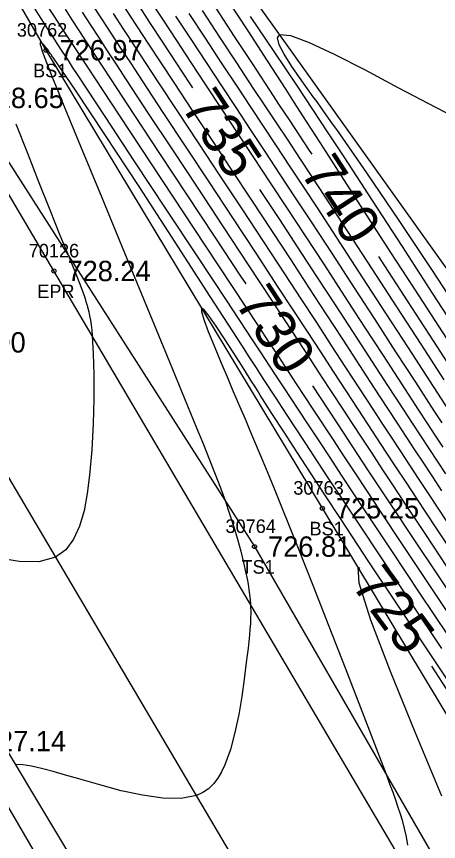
# Model space of a CAD drawing. Extents: x 1376587 to 1378239, y 1000335 to 1003031.
# Drawn here: x 1377030.7 to 1377061.8, y 1002189 to 1002249.8 of the extents above; entities that cross this region are included whole.
import ezdxf

# ---------------------------------------------------------------- set-up
doc = ezdxf.new("R2010")
doc.units = 0
for name, color, linetype in [('RD_DTM_BkLn1', 7, 'Continuous'), ('RD_DTM_BkLn2', 7, 'Continuous'), ('RD_DTM_BkLn_txCode', 7, 'Continuous'), ('RD_DTM_Major1', 7, 'Continuous'), ('RD_DTM_Major1_Lbl', 7, 'Continuous'), ('RD_DTM_Minor1', 7, 'Continuous'), ('RD_EX_Road', 7, 'Continuous'), ('RD_EX_Road_txCode', 7, 'Continuous'), ('RD_EX_TX_Misc_ELEV', 7, 'Continuous'), ('RD_EX_TX_Road_ELEV', 7, 'Continuous'), ('RD_HC_Survey_ELEV', 7, 'Continuous'), ('RD_SMD_Locator', 7, 'Continuous')]:
    doc.layers.add(name, color=color, linetype=linetype)

msp = doc.modelspace()

# ---------------------------------------------------------------- linework, layer by layer
at = {"layer": 'RD_DTM_BkLn1'}
msp.add_lwpolyline([(1377340.411, 1001702.156), (1377308.865, 1001753.727), (1377278.246, 1001805.238), (1377245.962, 1001858.008), (1377214.824, 1001910.42), (1377182.966, 1001962.109), (1377151.242, 1002015.115), (1377120.387, 1002065.538), (1377089.615, 1002116.564), (1377055.769, 1002172.475), (1377024.269, 1002225.826), (1377004.131, 1002257.876), (1377003.447, 1002259.314)], dxfattribs=at)
at = {"layer": 'RD_DTM_BkLn2'}
for points in [[(1377334.808, 1002026.055), (1377284.229, 1002013.339), (1377249.257, 1001988.727), (1377213.659, 1001973.589), (1377188.957, 1002014.33), (1377158.44, 1002070.963), (1377139.047, 1002104.941), (1377113.892, 1002149.475), (1377071.66, 1002218.399), (1377041.895, 1002260.076), (1377023.693, 1002288.088), (1377010.927, 1002302.495), (1376992.725, 1002332.02), (1376976.352, 1002351.559)], [(1376977.592, 1002343.743), (1376991.525, 1002318.779), (1377012.226, 1002283.102), (1377032.893, 1002247.364), (1377053.281, 1002213.6), (1377075.695, 1002176.413), (1377096.747, 1002142.056), (1377117.513, 1002106.979), (1377138.493, 1002071.226), (1377160.243, 1002035.712), (1377181.074, 1001999.107), (1377204.311, 1001959.476)], [(1376971.766, 1002339.684), (1376984.16, 1002314.581), (1377005.368, 1002280.112), (1377027.082, 1002243.848), (1377048.279, 1002210.776), (1377069.87, 1002173.423), (1377092.065, 1002138.92), (1377112.017, 1002104.252), (1377133.641, 1002068.495), (1377155.53, 1002032.726), (1377177.087, 1001996.618), (1377201.678, 1001958.67), (1377205.328, 1001957.618)], [(1376933.477, 1002336.978), (1376936.207, 1002337.361), (1376942.118, 1002334.622), (1376963.252, 1002302.727), (1376984.874, 1002266.163), (1377004.611, 1002231.868), (1377027.248, 1002196.435), (1377047.864, 1002161.082), (1377069.437, 1002124.09), (1377090.339, 1002090.957), (1377112.039, 1002054.903), (1377133.555, 1002020.982), (1377142.847, 1002000.419), (1377146.96, 1001979.874), (1377168.451, 1001949.096), (1377180.608, 1001931.393), (1377190.285, 1001911.959), (1377184.466, 1001904.154), (1377176.345, 1001916.445), (1377168.914, 1001925.218), (1377157.418, 1001940.596), (1377135.248, 1001988.16)]]:
    msp.add_lwpolyline(points, dxfattribs=at)
at = {"layer": 'RD_DTM_Major1'}
for points in [[(1377047.654, 1002230.136), (1377047.278, 1002230.706), (1377045.332, 1002233.655), (1377043.313, 1002236.712), (1377041.307, 1002239.747), (1377039.402, 1002242.635), (1377037.683, 1002245.247), (1377036.45, 1002247.128), (1377035.887, 1002247.991), (1377035.351, 1002248.815), (1377034.836, 1002249.609), (1377034.335, 1002250.385)], [(1377039.619, 1002250.823), (1377040.539, 1002249.408), (1377041.491, 1002247.952), (1377042.479, 1002246.45), (1377043.503, 1002244.897), (1377043.699, 1002244.599)], [(1377052.52, 1002239.698), (1377052.342, 1002239.969), (1377051.592, 1002241.11), (1377050.859, 1002242.222), (1377050.133, 1002243.323), (1377049.403, 1002244.431), (1377048.122, 1002246.374), (1377046.801, 1002248.384), (1377045.448, 1002250.456)], [(1377048.659, 1002237.089), (1377048.743, 1002236.961), (1377050.111, 1002234.884), (1377051.48, 1002232.797), (1377052.863, 1002230.683), (1377054.226, 1002228.592), (1377055.558, 1002226.545), (1377058.086, 1002222.657), (1377059.26, 1002220.855), (1377059.897, 1002219.88), (1377060.517, 1002218.933), (1377061.129, 1002218.001), (1377061.74, 1002217.072), (1377062.358, 1002216.135)], [(1377063.278, 1002223.158), (1377061.471, 1002225.943), (1377059.555, 1002228.897), (1377057.609, 1002231.895), (1377057.437, 1002232.16)], [(1377063.681, 1002205.847), (1377061.837, 1002208.615), (1377060.059, 1002211.29), (1377058.41, 1002213.774), (1377056.693, 1002216.37), (1377055.907, 1002217.56), (1377055.156, 1002218.702), (1377054.426, 1002219.812), (1377053.708, 1002220.907), (1377052.592, 1002222.612)], [(1377056.038, 1002209.158), (1377055.896, 1002209.261), (1377055.967, 1002208.09), (1377056.836, 1002205.385), (1377058.287, 1002201.579), (1377060.105, 1002197.107), (1377062.074, 1002192.404)], [(1377062.661, 1002199.943), (1377061.366, 1002201.963)]]:
    msp.add_lwpolyline(points, dxfattribs=at)
at = {"layer": 'RD_DTM_Minor1'}
for points in [[(1377040.497, 1002251.188), (1377041.5, 1002249.644), (1377042.531, 1002248.068), (1377043.589, 1002246.459), (1377044.673, 1002244.817), (1377045.828, 1002243.067), (1377047.01, 1002241.28), (1377048.215, 1002239.455), (1377049.444, 1002237.593), (1377050.693, 1002235.694), (1377051.963, 1002233.758), (1377053.43, 1002231.513), (1377054.9, 1002229.257), (1377056.351, 1002227.025), (1377057.763, 1002224.852), (1377059.114, 1002222.773), (1377060.383, 1002220.825), (1377060.995, 1002219.888), (1377061.588, 1002218.982), (1377062.167, 1002218.099)], [(1377062.452, 1002226.103), (1377060.413, 1002229.248), (1377058.34, 1002232.452), (1377056.326, 1002235.57), (1377054.467, 1002238.454), (1377053.774, 1002239.53), (1377053.113, 1002240.558), (1377052.475, 1002241.551), (1377051.85, 1002242.523), (1377051.231, 1002243.488), (1377050.607, 1002244.461), (1377049.243, 1002246.582), (1377047.817, 1002248.781), (1377046.329, 1002251.04)], [(1377062.58, 1002204.189), (1377060.477, 1002207.347), (1377058.453, 1002210.39), (1377056.596, 1002213.187), (1377055.612, 1002214.673), (1377054.701, 1002216.049), (1377053.85, 1002217.339), (1377053.042, 1002218.563), (1377052.264, 1002219.744), (1377051.5, 1002220.904), (1377050.987, 1002221.685), (1377050.465, 1002222.478), (1377049.926, 1002223.297), (1377049.363, 1002224.152), (1377048.767, 1002225.057), (1377048.129, 1002226.024), (1377046.208, 1002228.93), (1377044.048, 1002232.195), (1377041.761, 1002235.651), (1377039.461, 1002239.132), (1377037.261, 1002242.469), (1377035.273, 1002245.497), (1377034.867, 1002246.118), (1377034.476, 1002246.717), (1377034.097, 1002247.298), (1377033.73, 1002247.863), (1377033.372, 1002248.416), (1377033.021, 1002248.957), (1377032.068, 1002250.44)], [(1377063.13, 1002205.019), (1377061.156, 1002207.983), (1377059.253, 1002210.843), (1377057.5, 1002213.485), (1377056.563, 1002214.899), (1377055.692, 1002216.216), (1377054.874, 1002217.456), (1377054.095, 1002218.638), (1377052.606, 1002220.905), (1377051.996, 1002221.835), (1377051.376, 1002222.781), (1377050.735, 1002223.759), (1377050.062, 1002224.785), (1377049.346, 1002225.876), (1377048.575, 1002227.047), (1377046.713, 1002229.874), (1377044.652, 1002232.994), (1377038.34, 1002242.538), (1377036.544, 1002245.255), (1377036.024, 1002246.042), (1377035.534, 1002246.785), (1377035.07, 1002247.488), (1377034.628, 1002248.161), (1377034.202, 1002248.809), (1377033.789, 1002249.44), (1377033.013, 1002250.632)], [(1377063.211, 1002209.865), (1377061.68, 1002212.167), (1377060.245, 1002214.33), (1377059.46, 1002215.517), (1377058.713, 1002216.649), (1377057.995, 1002217.738), (1377057.296, 1002218.801), (1377056.606, 1002219.853), (1377055.916, 1002220.907), (1377055.027, 1002222.267), (1377054.114, 1002223.668), (1377053.166, 1002225.12), (1377052.177, 1002226.637), (1377051.136, 1002228.228), (1377050.036, 1002229.907), (1377048.399, 1002232.396), (1377046.681, 1002235.003), (1377044.931, 1002237.653), (1377041.544, 1002242.782), (1377040.008, 1002245.112), (1377039.195, 1002246.348), (1377038.432, 1002247.511), (1377037.711, 1002248.613), (1377037.025, 1002249.669), (1377036.365, 1002250.689)], [(1377038.748, 1002250.449), (1377039.587, 1002249.158), (1377040.462, 1002247.821), (1377041.376, 1002246.429), (1377042.336, 1002244.972), (1377043.686, 1002242.926), (1377045.103, 1002240.781), (1377046.565, 1002238.568), (1377048.05, 1002236.318), (1377049.535, 1002234.063), (1377050.999, 1002231.834), (1377052.292, 1002229.857), (1377053.548, 1002227.932), (1377054.763, 1002226.066), (1377057.062, 1002222.534), (1377058.141, 1002220.879), (1377058.799, 1002219.873), (1377059.444, 1002218.888), (1377060.087, 1002217.909), (1377060.734, 1002216.926), (1377061.396, 1002215.923), (1377062.079, 1002214.89)], [(1377044.413, 1002250.28), (1377045.686, 1002248.335), (1377046.949, 1002246.423), (1377048.19, 1002244.55), (1377049.036, 1002243.275), (1377049.877, 1002242.005), (1377050.727, 1002240.721), (1377051.596, 1002239.404), (1377052.496, 1002238.036), (1377053.439, 1002236.598), (1377055.136, 1002233.998), (1377056.927, 1002231.247), (1377058.747, 1002228.442), (1377060.536, 1002225.685), (1377062.231, 1002223.074)], [(1377062.523, 1002209.242), (1377060.869, 1002211.73), (1377059.327, 1002214.054), (1377058.49, 1002215.317), (1377057.701, 1002216.511), (1377056.949, 1002217.652), (1377056.223, 1002218.755), (1377055.514, 1002219.836), (1377054.81, 1002220.91), (1377054.015, 1002222.125), (1377053.203, 1002223.368), (1377052.362, 1002224.656), (1377051.481, 1002226.004), (1377050.548, 1002227.429), (1377049.552, 1002228.947), (1377047.838, 1002231.553), (1377046.004, 1002234.333), (1377044.12, 1002237.185), (1377042.254, 1002240.011), (1377040.473, 1002242.708), (1377038.847, 1002245.178), (1377038.117, 1002246.287), (1377037.435, 1002247.329), (1377036.791, 1002248.314), (1377036.179, 1002249.254), (1377035.591, 1002250.162)], [(1377062.492, 1002212.604), (1377061.163, 1002214.608), (1377060.429, 1002215.718), (1377059.725, 1002216.785), (1377059.041, 1002217.823), (1377058.37, 1002218.845), (1377057.701, 1002219.865), (1377057.026, 1002220.896), (1377056.043, 1002222.404), (1377055.024, 1002223.967), (1377053.966, 1002225.591), (1377052.865, 1002227.28), (1377051.717, 1002229.038), (1377050.518, 1002230.87), (1377048.965, 1002233.234), (1377047.362, 1002235.665), (1377045.746, 1002238.114), (1377044.152, 1002240.527), (1377042.615, 1002242.854), (1377041.171, 1002245.044), (1377040.282, 1002246.395), (1377039.442, 1002247.674), (1377038.644, 1002248.894), (1377037.882, 1002250.065)], [(1377042.464, 1002249.868), (1377043.576, 1002248.171), (1377044.703, 1002246.458), (1377045.843, 1002244.733), (1377046.898, 1002243.138), (1377047.964, 1002241.526), (1377049.047, 1002239.887), (1377050.152, 1002238.212), (1377051.285, 1002236.49), (1377052.45, 1002234.712), (1377053.997, 1002232.345), (1377055.573, 1002229.924), (1377057.146, 1002227.503), (1377058.682, 1002225.138), (1377060.147, 1002222.882), (1377061.509, 1002220.791), (1377062.093, 1002219.896)], [(1377043.437, 1002250.08), (1377044.629, 1002248.26), (1377045.824, 1002246.446), (1377047.015, 1002244.646), (1377047.967, 1002243.209), (1377048.92, 1002241.769), (1377049.884, 1002240.31), (1377050.869, 1002238.816), (1377051.885, 1002237.272), (1377052.942, 1002235.66), (1377054.565, 1002233.175), (1377056.248, 1002230.589), (1377057.944, 1002227.977), (1377059.606, 1002225.417), (1377061.186, 1002222.983), (1377062.637, 1002220.752)], [(1377063.563, 1002226.144), (1377061.417, 1002229.461), (1377059.195, 1002232.892), (1377056.989, 1002236.287), (1377054.893, 1002239.494), (1377054.301, 1002240.394), (1377053.723, 1002241.272), (1377053.154, 1002242.134), (1377052.587, 1002242.988), (1377052.02, 1002243.842), (1377051.446, 1002244.703), (1377049.734, 1002247.258), (1377047.982, 1002249.86)], [(1377063.826, 1002227.428), (1377061.402, 1002231.114), (1377058.945, 1002234.805), (1377056.558, 1002238.331), (1377054.343, 1002241.52), (1377054.04, 1002241.948), (1377053.743, 1002242.366), (1377053.452, 1002242.773), (1377053.167, 1002243.169), (1377052.889, 1002243.556), (1377052.617, 1002243.933), (1377051.765, 1002245.118), (1377051.032, 1002246.17), (1377050.46, 1002247.063), (1377050.093, 1002247.77), (1377049.974, 1002248.266), (1377050.146, 1002248.523), (1377050.937, 1002248.456), (1377052.304, 1002247.944), (1377054.151, 1002247.074), (1377056.384, 1002245.931), (1377058.906, 1002244.603), (1377061.622, 1002243.174), (1377065.499, 1002241.168)], [(1377062.083, 1002203.27), (1377059.869, 1002206.591), (1377057.74, 1002209.787), (1377055.797, 1002212.711), (1377054.771, 1002214.257), (1377053.821, 1002215.692), (1377052.923, 1002217.052), (1377052.054, 1002218.371), (1377051.193, 1002219.686), (1377050.315, 1002221.03), (1377049.869, 1002221.716), (1377048.929, 1002223.164), (1377048.426, 1002223.939), (1377047.896, 1002224.758), (1377047.334, 1002225.627), (1377045.017, 1002229.21), (1377042.424, 1002233.215), (1377039.764, 1002237.306), (1377037.247, 1002241.15), (1377035.083, 1002244.411), (1377033.482, 1002246.754), (1377033.434, 1002246.822), (1377033.388, 1002246.888), (1377033.342, 1002246.952), (1377033.297, 1002247.014), (1377033.212, 1002247.133), (1377033.062, 1002247.338), (1377032.929, 1002247.514), (1377032.814, 1002247.662), (1377032.715, 1002247.779), (1377032.633, 1002247.868), (1377032.568, 1002247.926), (1377032.519, 1002247.955), (1377032.486, 1002247.953), (1377032.47, 1002247.921), (1377032.469, 1002247.859), (1377032.482, 1002247.77), (1377032.51, 1002247.653), (1377032.627, 1002247.282), (1377032.811, 1002246.775), (1377033.057, 1002246.137), (1377033.363, 1002245.376), (1377033.721, 1002244.496), (1377034.128, 1002243.504), (1377035.455, 1002240.281), (1377037.008, 1002236.51), (1377038.687, 1002232.437), (1377040.388, 1002228.312), (1377042.008, 1002224.382), (1377044.004, 1002219.539), (1377044.511, 1002218.301), (1377044.97, 1002217.163), (1377045.386, 1002216.106), (1377045.765, 1002215.111), (1377046.111, 1002214.159), (1377046.446, 1002213.178), (1377046.75, 1002212.228), (1377047.021, 1002211.313), (1377047.261, 1002210.436), (1377047.469, 1002209.603), (1377047.645, 1002208.817), (1377047.729, 1002208.404), (1377047.802, 1002208.004), (1377047.865, 1002207.617), (1377047.916, 1002207.24), (1377047.955, 1002206.872), (1377047.982, 1002206.511), (1377047.992, 1002206.277), (1377047.997, 1002206.045), (1377047.998, 1002205.812), (1377047.993, 1002205.577), (1377047.985, 1002205.339), (1377047.972, 1002205.096), (1377047.942, 1002204.674), (1377047.903, 1002204.232), (1377047.855, 1002203.769), (1377047.8, 1002203.28), (1377047.738, 1002202.765), (1377047.671, 1002202.219), (1377047.519, 1002201.011), (1377047.337, 1002199.717), (1377047.114, 1002198.388), (1377046.839, 1002197.073), (1377046.5, 1002195.822), (1377046.087, 1002194.686), (1377045.843, 1002194.167), (1377045.568, 1002193.697), (1377045.254, 1002193.281), (1377044.892, 1002192.925), (1377044.476, 1002192.635), (1377043.995, 1002192.416), (1377042.86, 1002192.201), (1377041.514, 1002192.226), (1377040.022, 1002192.438), (1377038.45, 1002192.781), (1377036.862, 1002193.202), (1377035.324, 1002193.645), (1377034.339, 1002193.932), (1377033.419, 1002194.192), (1377032.579, 1002194.411), (1377031.831, 1002194.577), (1377031.188, 1002194.678), (1377030.663, 1002194.7)], [(1377030.679, 1002241.929), (1377031.526, 1002239.764), (1377032.374, 1002237.623), (1377033.188, 1002235.588), (1377033.934, 1002233.738), (1377034.578, 1002232.153), (1377034.878, 1002231.415), (1377035.14, 1002230.767), (1377035.367, 1002230.194), (1377035.563, 1002229.68), (1377035.731, 1002229.208), (1377035.874, 1002228.765), (1377035.895, 1002228.695), (1377035.915, 1002228.626), (1377035.935, 1002228.557), (1377035.954, 1002228.488), (1377035.973, 1002228.419), (1377035.992, 1002228.349), (1377036.06, 1002228.071), (1377036.121, 1002227.779), (1377036.177, 1002227.464), (1377036.226, 1002227.118), (1377036.27, 1002226.733), (1377036.31, 1002226.301), (1377036.386, 1002225.004), (1377036.428, 1002223.44), (1377036.428, 1002221.684), (1377036.381, 1002219.815), (1377036.28, 1002217.908), (1377036.118, 1002216.04), (1377035.944, 1002214.678), (1377035.706, 1002213.416), (1377035.378, 1002212.286), (1377034.936, 1002211.319), (1377034.356, 1002210.546), (1377033.613, 1002210), (1377032.384, 1002209.655), (1377030.915, 1002209.664), (1377029.284, 1002209.943)], [(1377063.846, 1002198.954), (1377061.486, 1002202.491), (1377059.092, 1002206.086), (1377056.768, 1002209.586), (1377054.615, 1002212.841), (1377053.464, 1002214.589), (1377052.397, 1002216.219), (1377051.399, 1002217.75), (1377050.459, 1002219.202), (1377049.564, 1002220.594), (1377048.701, 1002221.946), (1377048.496, 1002222.269), (1377048.292, 1002222.59), (1377048.089, 1002222.911), (1377047.685, 1002223.549), (1377047.484, 1002223.867), (1377046.754, 1002225.02), (1377046.063, 1002226.097), (1377045.446, 1002227.034), (1377044.936, 1002227.766), (1377044.566, 1002228.229), (1377044.369, 1002228.36), (1377044.369, 1002228.105), (1377044.548, 1002227.506), (1377044.871, 1002226.635), (1377045.3, 1002225.565), (1377045.797, 1002224.37), (1377046.327, 1002223.121), (1377046.642, 1002222.382), (1377046.956, 1002221.648), (1377047.27, 1002220.915), (1377047.583, 1002220.182), (1377047.896, 1002219.446), (1377048.211, 1002218.703), (1377048.705, 1002217.528), (1377049.209, 1002216.315), (1377049.729, 1002215.05), (1377050.273, 1002213.716), (1377050.846, 1002212.296), (1377051.455, 1002210.775), (1377052.581, 1002207.938), (1377053.772, 1002204.911), (1377054.968, 1002201.848), (1377056.107, 1002198.905), (1377057.132, 1002196.234), (1377057.981, 1002193.991), (1377058.241, 1002193.294), (1377058.471, 1002192.666), (1377058.675, 1002192.094), (1377058.855, 1002191.568), (1377059.015, 1002191.074), (1377059.158, 1002190.601), (1377059.324, 1002189.989), (1377059.461, 1002189.381), (1377059.566, 1002188.763)]]:
    msp.add_lwpolyline(points, dxfattribs=at)
at = {"layer": 'RD_EX_Road'}
for points in [[(1377350.339, 1001708.261), (1377317.923, 1001758.892), (1377286.961, 1001809.893), (1377254.767, 1001863.401), (1377224.604, 1001914.857), (1377192.26, 1001967.361), (1377160.973, 1002019.841), (1377129.715, 1002070.663), (1377099.389, 1002121.709), (1377064.159, 1002179.082), (1377033.485, 1002231.09), (1377014.7, 1002262.97), (1377013.314, 1002264.907)], [(1377330.916, 1001696.377), (1377301.062, 1001747.923), (1377269.086, 1001800.224), (1377238.031, 1001851.797), (1377206.51, 1001905.086), (1377174.784, 1001956.207), (1377142.237, 1002010.206), (1377112.371, 1002059.861), (1377081.07, 1002112.138), (1377047.747, 1002166.267), (1377015.04, 1002220.702), (1376995.387, 1002252.515), (1376994.747, 1002253.913)]]:
    msp.add_lwpolyline(points, dxfattribs=at)
at = {"layer": 'RD_SMD_Locator'}
for centre in [(1377032.893, 1002247.364), (1377033.485, 1002231.09), (1377053.281, 1002213.6), (1377048.279, 1002210.776)]:
    msp.add_circle(centre, 0.15, dxfattribs=at)

# ---------------------------------------------------------------- texts
at = {"layer": 'RD_DTM_BkLn_txCode'}
for s, p in [('30762', (1377030.751, 1002248.364)), ('BS1', (1377031.948, 1002245.364)), ('30763', (1377051.139, 1002214.6)), ('30764', (1377046.137, 1002211.776)), ('BS1', (1377052.336, 1002211.6)), ('TS1', (1377047.318, 1002208.776))]:
    msp.add_text(s, height=1, dxfattribs=at).set_placement(p)
at = {"layer": 'RD_DTM_Major1_Lbl'}
for s, rotation, p in [('735', 303.43973, (1377042.806, 1002243.231)), ('740', 303.114, (1377051.597, 1002238.377)), ('730', 303.27796, (1377046.76, 1002228.772)), ('725', 306.52157, (1377055.361, 1002207.957))]:
    msp.add_text(s, height=3, rotation=rotation, dxfattribs=at).set_placement(p)
at = {"layer": 'RD_EX_Road_txCode'}
for s, p in [('70126', (1377031.627, 1002232.09)), ('EPR', (1377032.257, 1002229.09))]:
    msp.add_text(s, height=1, dxfattribs=at).set_placement(p)
at = {"layer": 'RD_EX_TX_Misc_ELEV'}
for s, p in [('726.97', (1377033.893, 1002246.614)), ('728.65', (1377028.082, 1002243.098)), ('725.25', (1377054.281, 1002212.85)), ('726.81', (1377049.279, 1002210.026)), ('727.14', (1377028.248, 1002195.685))]:
    msp.add_text(s, height=1.5, dxfattribs=at).set_placement(p)
at = {"layer": 'RD_EX_TX_Road_ELEV'}
msp.add_text('728.24', height=1.5, dxfattribs=at).set_placement((1377034.485, 1002230.34))
at = {"layer": 'RD_HC_Survey_ELEV'}
msp.add_text('728.90', height=1.5, dxfattribs=at).set_placement((1377025.269, 1002225.076))

doc.saveas('drawing.dxf')
